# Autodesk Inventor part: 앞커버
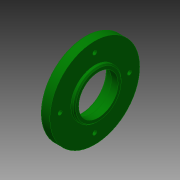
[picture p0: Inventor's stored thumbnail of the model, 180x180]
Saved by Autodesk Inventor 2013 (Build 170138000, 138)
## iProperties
Created: 2015-09
Part Number: 앞커버
Material: 알루미늄 6061
Document SubType Name: Modeling
Designer: mduedu
Density: 2.71 g/cm^3
Mass: 58.9874 g
Surface Area: 98.7754 cm^2
Volume: 21.7666 cm^3
Author: mduedu
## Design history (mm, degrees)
sketch "스케치1"
  geometry: L1 (-8.5, 67)-(-11.5, 67); L2 (-11.5, 67)-(-11.5, 84.5); L3 (-11.5, 84.5)-(-19.5, 84.5); L4 (-19.5, 84.5)-(-19.5, 70.5); L5 (-22.5, 70.5)-(-22.5, 58); L6 (-22.5, 58)-(-8.5, 58); L7 (-8.5, 58)-(-8.5, 67); L8 (-79.5, 39.5)-(-79.5, 54.5) reference; L9 (48.5, 54.5)-(48.5, 39.5) reference; L10 (-79.5, 47)-(48.5, 47); L11 (-19.5, 70.5)-(-22.5, 70.5); 3 further points
  constraints: 18 end point, 6 parallel, 4 midpoint, 1 horizontal, 1 perpendicular, 1 vertical alignment
  dimensions: "d0" = 14 distance between parallel lines of L7 L5; "d2" = 22 diameter of L6 L10; "d3" = 40 diameter of L1 L10; "d5" = 3 distance of L1.start L1.end; "d6" = 75 diameter of L3 L10; "d7" = 8 distance of L2.end L3.end; "d8" = 47 diameter of L4.end L10
revolve "회전1" sketch "스케치1" stored, may be unused: angle "d4" = 90 deg
sketch "스케치2"
  geometry: C1 r 37.5 at (0, 0) reference; 2 further points
  constraints: 1 coincident
hole "구멍1" sketch "스케치2" at (0, 0) diameter "d11" = 33; stored, may be unused: countersink angle "d15" = 90 deg, drill point angle "d17" = 0 deg; dims "d12" = 6, "d13" = 4, "d14" = 2, "d16" = 3
fillet "모깎기1" dims "d18" = 3
fillet "모깎기2" dims "d19" = 1
sketch "스케치3"
  geometry: C1 r 37.5 at (0, 0) reference; 2 further points
  constraints: 1 coincident
hole "구멍2" sketch "스케치3" at (0, 0) diameter "d20" = 32; stored, may be unused: countersink angle "d24" = 90 deg, drill point angle "d26" = 0 deg; dims "d21" = 6, "d22" = 4, "d23" = 2, "d25" = 8.3
fillet "모깎기3" dims "d27" = 0.4
chamfer "모따기1" distance "d28" = 0.8; stored, may be unused: second distance "d29" = 2, angle "d30" = 30 deg
sketch "스케치7" dims "d56" = 58
  geometry: C1 r 37.5 at (0, 0) reference; 5 further points
  constraints: 2 vertical alignment, 1 coincident, 7 other
  dimensions: "d59" = 360 deg dimension on C1.centre point (0, 29) (derived)
hole "구멍4" sketch "스케치7" at (0, 29), (-29, 0), (0, -29), (29, 0) diameter "d48" = 3.4; stored, may be unused: countersink angle "d52" = 90 deg, drill point angle "d54" = 0 deg; dims "d49" = 6, "d50" = 6.5, "d51" = 3.4, "d53" = 8
chamfer "모따기2" distance "d61" = 1; stored, may be unused: second distance "d62" = 2, angle "d63" = 45 deg
node "솔리드1"
node "참조1"
node "참조2"
